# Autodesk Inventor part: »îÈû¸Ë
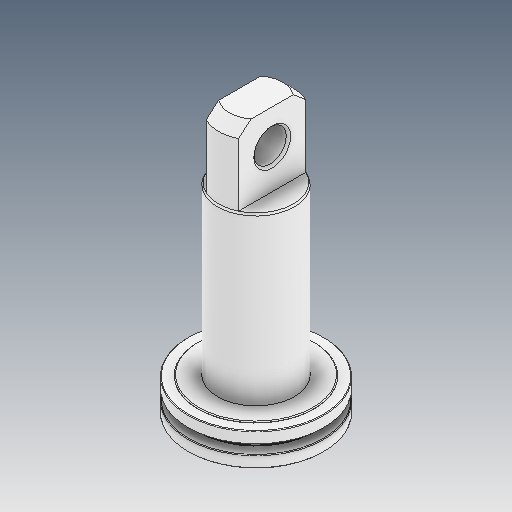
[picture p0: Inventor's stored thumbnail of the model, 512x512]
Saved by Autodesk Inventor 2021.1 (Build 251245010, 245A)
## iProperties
Created: 2021-05
Part Number: »îÈû¸Ë
Material: Ogólny
Document SubType Name: Modeling
Designer: user
Density: 1 g/cm^3
Appearance: Domyślna
Author: user
Revision Number: ÈÎºÎ
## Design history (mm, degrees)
feature "ÊäÈë1"
node "Bryła1"
